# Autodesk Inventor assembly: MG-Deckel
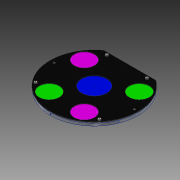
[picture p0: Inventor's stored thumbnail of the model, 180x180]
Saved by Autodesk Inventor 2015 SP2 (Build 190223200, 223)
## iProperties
Created: 2015-09
Part Number: MG-Deckel
Document SubType Name: Assembly
Designer: ryll
Mass: 34.1034 g
Surface Area: 611.258 cm^2
Volume: 29.2383 cm^3
Density: 1.16639 g/cm^3
Author: ryll
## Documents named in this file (8)
- D:\TIGERs GIT\Hardware\mechanik\2016\Inventor\Gehäuse\MG-Deckel.iam
- D:\TIGERs GIT\Hardware\mechanik\2016\Inventor\Gehäuse\Deckel.ipt
- Deckel.ipt
- D:\TIGERs GIT\Hardware\mechanik\2016\Inventor\Kaufteile\Papier 40mm.ipt
- D:\TIGERs GIT\Hardware\mechanik\2016\Inventor\Kaufteile\Papier 50mm.ipt
- D:\TIGERs GIT\Hardware\mechanik\2016\Inventor\Gehäuse\Verbindungsring Deckel.ipt
- D:\TIGERs GIT\Hardware\mechanik\2016\Inventor\Gehäuse\Verbindungplatte Deckel.ipt
- D:\TIGERs GIT\Hardware\mechanik\2016\Inventor\Inhaltscenter\de-DE\ISO 1207(1)\ISO 1207 - M3 x 8DIN EN ISO.ipt
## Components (12 placed, 6 different names)
1. Deckel:1 — Einfügen:1, Einfügen:2, Einfügen:3, Einfügen:4, Einfügen:5, Einfügen:8, Einfügen:9, Einfügen:10, Einfügen:11, Einfügen:12, Einfügen:13
2. Papier 40mm:1 — Einfügen:3
3. Papier 40mm:2 — Einfügen:1
4. Papier 40mm:3 — Einfügen:5
5. Papier 40mm:4 — Einfügen:4
6. Papier 50mm:1 — Einfügen:2
7. Verbindungsring Deckel:1 — Einfügen:6, Einfügen:7
8. Verbindungsplatte Deckel:1 — Einfügen:6, Einfügen:7, Einfügen:8, Einfügen:9
9. DIN EN ISO 1207 M3 x 8:1 — Einfügen:10
10. DIN EN ISO 1207 M3 x 8:2 — Einfügen:11
11. DIN EN ISO 1207 M3 x 8:3 — Einfügen:12
12. DIN EN ISO 1207 M3 x 8:4 — Einfügen:13
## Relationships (13: Insert 13)
- Einfügen:1 [Insert]: Deckel:1 ↔ Papier 40mm:2
- Einfügen:2 [Insert]: Deckel:1 ↔ Papier 50mm:1
- Einfügen:3 [Insert]: Deckel:1 ↔ Papier 40mm:1
- Einfügen:4 [Insert]: Deckel:1 ↔ Papier 40mm:4
- Einfügen:5 [Insert]: Deckel:1 ↔ Papier 40mm:3
- Einfügen:6 [Insert]: Verbindungsring Deckel:1 ↔ Verbindungsplatte Deckel:1
- Einfügen:7 [Insert]: Verbindungsring Deckel:1 ↔ Verbindungsplatte Deckel:1
- Einfügen:8 [Insert]: Deckel:1 ↔ Verbindungsplatte Deckel:1
- Einfügen:9 [Insert]: Deckel:1 ↔ Verbindungsplatte Deckel:1
- Einfügen:10 [Insert]: Deckel:1 ↔ DIN EN ISO 1207 M3 x 8:1
- Einfügen:11 [Insert]: Deckel:1 ↔ DIN EN ISO 1207 M3 x 8:2
- Einfügen:12 [Insert]: Deckel:1 ↔ DIN EN ISO 1207 M3 x 8:3
- Einfügen:13 [Insert]: Deckel:1 ↔ DIN EN ISO 1207 M3 x 8:4
